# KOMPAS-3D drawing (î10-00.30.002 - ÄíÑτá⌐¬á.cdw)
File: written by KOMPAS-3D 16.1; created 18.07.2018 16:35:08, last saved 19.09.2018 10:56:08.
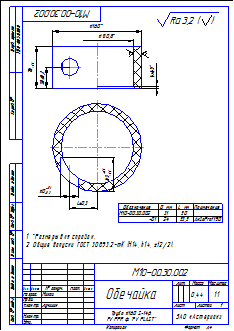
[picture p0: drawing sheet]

Sheet 1: A4, portrait

Title block, sheet 1: name: Обечайка; designation: М10-00.30.002; mass: 0,44; scale: 1:1; sheets: 1; organisation: ЗАО «Астерион»; sheet format: A4; stored path: Z:\Магна\Магна Ins\Магна ins 10\М10-00.00.000\3Д\М10-00.30.002 - Обечайка.cdw; drawn by: Милов; technical control: Лучихин

Views: Вид 1, Местный разрез 1, Вид:1, Проекционный вид 2, Вид 3
Referenced files in Z:\1 ПКИ 3D\Полипропиленовые фитинги, трубы\Трубы\: Труба 160 S=14,6 FV PPR ф. FV PLAST.m3d
Referenced files in Z:\Магна\Магна Ins\Магна ins 10\М10-00.00.000\3Д\: М10-00.30.002 - Обечайка.m3d
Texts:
  Труба  160 S=14,6
  FV PPR ф. "FV PLAST"
  D, мм
  L, мм
  АкваProf190
  Аквапроф
  *Размеры для справок.
  Общие допуски ГОСТ 30893.2-mK (H14, h14,  t2/2).
  Ra 3,2
  Ra 3,2 ( )
  Труба 160 S=14,6 FV PPR ф. FV PLAST
Dimensions and other numbers on the sheet: 31; 50; -01; 24; 53,5; 76; 38±0,2; 4; 130,8; 160; 63; 19,5; 1:1; 1; 0,44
